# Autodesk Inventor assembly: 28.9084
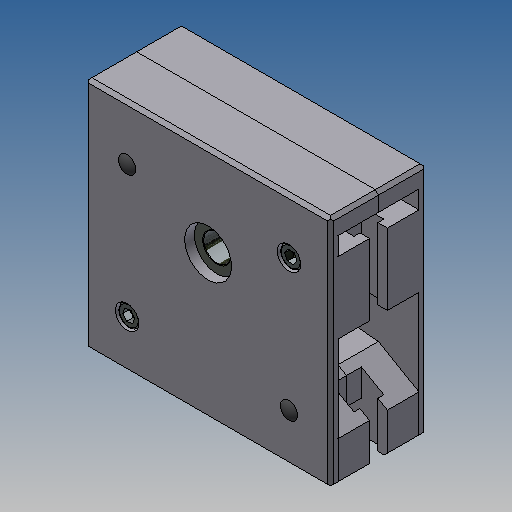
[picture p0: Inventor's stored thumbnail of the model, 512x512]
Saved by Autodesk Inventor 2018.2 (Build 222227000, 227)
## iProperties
Created: 2018-05
Part Number: 28.9084
Document SubType Name: Assembly
Designer: amoles
Vendor: S
Description: TIMING BELT PULLEY T45 .5inBORE-KEY
Stock Number: 28.0614 TIMING BELT PULLEY T45
Author: amoles
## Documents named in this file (12)
- Y:\INVENTOR LIBRARIES\PARTS LIBRARY\READY FOR USE MODULES LR\28.9084 TIMING BELT PULLEY T45 .5inBORE-KEY.iam
- Y:\INVENTOR LIBRARIES\PARTS LIBRARY\READY FOR USE MODULES LR\SUBCOMPONENTS\28.0614 TIMING BELT PULLEY T45 RIGHT PLATE.ipt
- Y:\INVENTOR LIBRARIES\PARTS LIBRARY\READY FOR USE MODULES LR\SUBCOMPONENTS\SHIM DIN 988 - 25 x 35 x 0,1.ipt
- 00005263.ipt
- Y:\INVENTOR LIBRARIES\PARTS LIBRARY\READY FOR USE MODULES LR\SUBCOMPONENTS\28.0083 BEARING.ipt
- Y:\INVENTOR LIBRARIES\PARTS LIBRARY\READY FOR USE MODULES LR\SUBCOMPONENTS\SHIM DIN 988 - 37 x 47 x 0,1.ipt
- 00005262.ipt
- Y:\INVENTOR LIBRARIES\PARTS LIBRARY\READY FOR USE MODULES LR\SUBCOMPONENTS\28.0614 TIMING BELT PULLEY T45 LEFT PLATE.ipt
- Y:\INVENTOR LIBRARIES\PARTS LIBRARY\FASTENING ELEMENTS\SCREWS CAP\M6X30 HIGH HEAD.ipt
- 00005264.ipt
- Y:\INVENTOR LIBRARIES\PARTS LIBRARY\END CAPS\22.1203 HOLE CAP M6.ipt
- Y:\INVENTOR LIBRARIES\PARTS LIBRARY\READY FOR USE MODULES LR\SUBCOMPONENTS\28.9084_1 T45 PULLEY .5inBORE-KEY..ipt
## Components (17 placed, 8 different names)
1. 28.0614 TIMING BELT PULLEY T45 RIGHT PLATE:1 — Flush:1, Flush:2, Flush:3, Mate:6, Mate:7, Angle:1, Insert:7, Insert:8, Insert:11, Insert:12, Mate:9
2. 28.9084_1 T45 PULLEY .5inBORE-KEY.:2 — Insert:1, Insert:2, Mate:1, Mate:3, Mate:6, Mate:8, Angle:2
3. 00005263:1 — Insert:1, Insert:3
4. 00005263:2 — Insert:2, Insert:4
5. 28.0083 BEARING:1 — Insert:4, Mate:4
6. 28.0083 BEARING:2 — Insert:3, Mate:2
7. 00005262:1 — Mate:1, Mate:2
8. 00005262:2 — Mate:3, Mate:4
9. 28.0614 TIMING BELT PULLEY T45 LEFT PLATE:1 — Mate:7, Mate:8, Angle:1, Insert:5, Insert:6, Insert:9, Insert:10, Mate:9, Angle:2
10. 00005264:1 — Insert:6
11. 00005264:2 — Insert:5
12. 00005264:3 — Insert:8
13. 00005264:4 — Insert:7
14. 22.1203 HOLE CAP M6:1 — Insert:9
15. 22.1203 HOLE CAP M6:2 — Insert:10
16. 22.1203 HOLE CAP M6:3 — Insert:12
17. 22.1203 HOLE CAP M6:4 — Insert:11
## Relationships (25: Insert 12, Mate 8, Flush 3, Angle 2)
- Flush:1: 28.0614 TIMING BELT PULLEY T45 RIGHT PLATE:1
- Flush:2: 28.0614 TIMING BELT PULLEY T45 RIGHT PLATE:1
- Flush:3: 28.0614 TIMING BELT PULLEY T45 RIGHT PLATE:1
- Insert:1: 28.9084_1 T45 PULLEY .5inBORE-KEY.:2 ↔ 00005263:1
- Insert:2: 28.9084_1 T45 PULLEY .5inBORE-KEY.:2 ↔ 00005263:2
- Insert:3: 00005263:1 ↔ 28.0083 BEARING:2
- Insert:4: 00005263:2 ↔ 28.0083 BEARING:1
- Mate:1: 28.9084_1 T45 PULLEY .5inBORE-KEY.:2 ↔ 00005262:1
- Mate:2: 28.0083 BEARING:2 ↔ 00005262:1
- Mate:3: 28.9084_1 T45 PULLEY .5inBORE-KEY.:2 ↔ 00005262:2
- Mate:4: 28.0083 BEARING:1 ↔ 00005262:2
- Mate:6: 28.0614 TIMING BELT PULLEY T45 RIGHT PLATE:1 ↔ 28.9084_1 T45 PULLEY .5inBORE-KEY.:2
- Mate:7: 28.0614 TIMING BELT PULLEY T45 RIGHT PLATE:1 ↔ 28.0614 TIMING BELT PULLEY T45 LEFT PLATE:1
- Mate:8: 28.9084_1 T45 PULLEY .5inBORE-KEY.:2 ↔ 28.0614 TIMING BELT PULLEY T45 LEFT PLATE:1
- Angle:1: 28.0614 TIMING BELT PULLEY T45 RIGHT PLATE:1 ↔ 28.0614 TIMING BELT PULLEY T45 LEFT PLATE:1
- Insert:5: 28.0614 TIMING BELT PULLEY T45 LEFT PLATE:1 ↔ 00005264:2
- Insert:6: 28.0614 TIMING BELT PULLEY T45 LEFT PLATE:1 ↔ 00005264:1
- Insert:7: 28.0614 TIMING BELT PULLEY T45 RIGHT PLATE:1 ↔ 00005264:4
- Insert:8: 28.0614 TIMING BELT PULLEY T45 RIGHT PLATE:1 ↔ 00005264:3
- Insert:9: 28.0614 TIMING BELT PULLEY T45 LEFT PLATE:1 ↔ 22.1203 HOLE CAP M6:1
- Insert:10: 28.0614 TIMING BELT PULLEY T45 LEFT PLATE:1 ↔ 22.1203 HOLE CAP M6:2
- Insert:11: 28.0614 TIMING BELT PULLEY T45 RIGHT PLATE:1 ↔ 22.1203 HOLE CAP M6:4
- Insert:12: 28.0614 TIMING BELT PULLEY T45 RIGHT PLATE:1 ↔ 22.1203 HOLE CAP M6:3
- Mate:9: 28.0614 TIMING BELT PULLEY T45 RIGHT PLATE:1 ↔ 28.0614 TIMING BELT PULLEY T45 LEFT PLATE:1
- Angle:2: 28.9084_1 T45 PULLEY .5inBORE-KEY.:2 ↔ 28.0614 TIMING BELT PULLEY T45 LEFT PLATE:1
